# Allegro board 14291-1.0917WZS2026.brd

Outline 221.8 x 181.97 mm; copper layers: TOP, L2VCC, L3, L4, L5GND, BOTTOM. Coordinates in mm from the lower left corner of the outline.

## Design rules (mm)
constraint set DEFAULT: min track width 0.127, pair gap 0.102
net group AUDIO_12MIL: nets CPVEE V3D3_STB
net group AUDIO_BEEP_15MIL: nets AUD_PORTA_L_HPMIC1 AUD_PORTA_R_HPMIC1
net group CL_CLK: nets CL_CLK CL_CLK_R
net group CL_DATA: nets CL_DATA CL_DATA_R
net group CL_RST#: nets CL_RST# CL_RST#_R
net group CLK_PCI_LPC: nets CLK_PCI_LPC PCI_CLK_LPC0
net group CLK_PCI_LPC_MEC: nets CLK_PCI_LPC_MEC PCI_CLK_LPC1
net group CPU_RXN_C_DGPU_TXN0: nets CPU_RXN_C_DGPU_TXN0 DGPU_TXN_CPU_RXN0
net group CPU_RXN_C_DGPU_TXN1: nets CPU_RXN_C_DGPU_TXN1 DGPU_TXN_CPU_RXN1
net group CPU_RXN_C_DGPU_TXN2: nets CPU_RXN_C_DGPU_TXN2 DGPU_TXN_CPU_RXN2
net group CPU_RXN_C_DGPU_TXN3: nets CPU_RXN_C_DGPU_TXN3 DGPU_TXN_CPU_RXN3
net group CPU_RXP_C_DGPU_TXP0: nets CPU_RXP_C_DGPU_TXP0 DGPU_TXP_CPU_RXP0
net group CPU_RXP_C_DGPU_TXP1: nets CPU_RXP_C_DGPU_TXP1 DGPU_TXP_CPU_RXP1
net group CPU_RXP_C_DGPU_TXP2: nets CPU_RXP_C_DGPU_TXP2 DGPU_TXP_CPU_RXP2
net group CPU_RXP_C_DGPU_TXP3: nets CPU_RXP_C_DGPU_TXP3 DGPU_TXP_CPU_RXP3
net group DDR3_A_ODT10_50R-MW: nets M_A_DIMA_ODT0 M_A_DIMA_ODT1
net group DDR3_B_ODT10_50R-MW: nets M_B_DIMB_ODT0 M_B_DIMB_ODT1
net group DGPU_RXN_C_CPU_TXN0: nets DGPU_RXN_C_CPU_TXN0 PEG_TX_CPU_N0
net group DGPU_RXN_C_CPU_TXN1: nets DGPU_RXN_C_CPU_TXN1 PEG_TX_CPU_N1
net group DGPU_RXN_C_CPU_TXN2: nets DGPU_RXN_C_CPU_TXN2 PEG_TX_CPU_N2
net group DGPU_RXN_C_CPU_TXN3: nets DGPU_RXN_C_CPU_TXN3 PEG_TX_CPU_N3
net group DGPU_RXP_C_CPU_TXP0: nets DGPU_RXP_C_CPU_TXP0 PEG_TX_CPU_P0
net group DGPU_RXP_C_CPU_TXP1: nets DGPU_RXP_C_CPU_TXP1 PEG_TX_CPU_P1
net group DGPU_RXP_C_CPU_TXP2: nets DGPU_RXP_C_CPU_TXP2 PEG_TX_CPU_P2
net group DGPU_RXP_C_CPU_TXP3: nets DGPU_RXP_C_CPU_TXP3 PEG_TX_CPU_P3
net group DMIC_CLK_EDP: nets DMIC_PCH_CLK DMIC_PCH_CLK_R
net group DMIC_DATA_EDP: nets DMIC_PCH_DATA DMIC_PCH_DATA_R
net group DP_USB_CPU_PN2: nets USB_CPU_PN2 USB_CPU_PP2
net group DP_USB_CPU_PN5: nets USB_CPU_PN5 USB_CPU_PP5
net group DP_USB_PN0_C: nets USB_PN0_C USB_PP0_C
net group EDP_AUX_CON_N: nets EDP_AUX_CON_N EDP_AUX_CPU_N
net group EDP_AUX_CON_P: nets EDP_AUX_CON_P EDP_AUX_CPU_P
net group EDP_TX_CON_N0: nets EDP_TX_CON_N0 EDP_TX_CPU_N0
net group EDP_TX_CON_N1: nets EDP_TX_CON_N1 EDP_TX_CPU_N1
net group EDP_TX_CON_P0: nets EDP_TX_CON_P0 EDP_TX_CPU_P0
net group EDP_TX_CON_P1: nets EDP_TX_CON_P1 EDP_TX_CPU_P1
net group FBA_VREF: nets FBA_VREF_0 FBA_VREF_1
net group I2C0_SCL_TCH_PAD: nets I2C0_SCL_TCH_PAD I2C1_SCL_R
net group I2C0_SDA_TCH_PAD: nets I2C0_SDA_TCH_PAD I2C1_SDA_R
net group OTHER_4MIL_8MIL: nets HOST_DEBUG_TX ICSP_CLR
net group PCH_SPI_CS2#: nets PCH_SPI_CS2# SPI_CS2#_R
net group PCIE_RX_CON_N6: nets PCIE_RX_CON_N6 PCIE_RX_CPU_N6
net group PCIE_RX_CON_P6: nets PCIE_RX_CON_P6 PCIE_RX_CPU_P6
net group PCIE_TX_CON_N5: nets PCIE_TX_CON_N5 PCIE_TX_CPU_N5
net group PCIE_TX_CON_N6: nets PCIE_TX_CON_N6 PCIE_TX_CPU_N6
net group PCIE_TX_CON_P5: nets PCIE_TX_CON_P5 PCIE_TX_CPU_P5
net group PCIE_TX_CON_P6: nets PCIE_TX_CON_P6 PCIE_TX_CPU_P6
net group PWR_VCCGT_VSN: nets PWR_VCCGT_VSN PWR_VCCGT_VSN_R
net group REF10M: nets PWR_VCCGT_DISB#_A VR_CAP
net group SPI1_HOLD_ROM_R: nets SPI1_HOLD_ROM_R SPI_HOLD_ROM
net group SPI-MWS: nets SPI_HOLD_CPU SPI_HOLD_ROM_R
net group SPI_CS_CPU_N1: nets SPI_CS_CPU_N1 SPI_CS_ROM_N1
net group USB30_TX_CPU_N1: nets USB3_PTX_CRX_N1_R USB30_TX_CPU_N1
net group USB30_TX_CPU_N2: nets USB3_PTX_CRX_N2_R USB30_TX_CPU_N2
net group USB30_TX_CPU_P1: nets USB3_PTX_CRX_P1_R USB30_TX_CPU_P1
net group USB30_TX_CPU_P2: nets USB3_PTX_CRX_P2_R USB30_TX_CPU_P2
net group USB_CON_PN6: nets USB_CON_PN6 USB_CPU_PN6
net group USB_CON_PN7: nets USB_CON_PN7 USB_CPU_PN7
net group USB_CON_PP6: nets USB_CON_PP6 USB_CPU_PP6
net group USB_CON_PP7: nets USB_CON_PP7 USB_CPU_PP7
net group USB_CPU_PN3: nets USB_CPU_PN3 USB_PN3_C
net group USB_CPU_PP3: nets USB_CPU_PP3 USB_PP3_C
net group X_CLK6MIL: nets CFG_RCOMP XCLK_BIASREF
net group AUDIO_BEEP_10MIL: nets AUD_HP1_JACK_L AUD_HP1_JACK_L1 AUD_HP1_JACK_R AUD_HP1_JACK_R1 AUD_PC_BEEP AUD_PC_BEEP_3246 AUD_PC_BEEP_C AUD_PC_BEEP_R AUD_SENSE AUD_SENSE_A AUD_VREF BEEP CBN CBP HDA_SPKR_R JACK_PLUG JACK_PLUG_DET KBC_BEEP_R LINE1-L_C LINE1-L_R LINE1_L LINE1_R LINE1_VREFO_L LINE1_VREFO_R MIC2_VREFO SPKR
net group CARD_12MIL: nets RSET
net group CFG_50R-MW: nets CFG0 CFG1 CFG2 CFG3 CFG4 CFG5 CFG6 CFG7 CFG8 CFG9 CFG10 CFG11 CFG12 CFG13 CFG14 CFG15 CFG16 CFG17 CFG18 CFG19
net group CLK_50R-MW: nets PEXTSTCLK_OUT PEXTSTCLK_OUT# VIDEO_CLK_XTAL_SS WLAN_CLKREQ_WLAN#
net group CODEC_BITCLK_R: nets CODEC_BITCLK_R HDA_BITCLK HDA_CODEC_BITCLK
net group CODEC_SDOUT_R: nets CODEC_SDOUT_R HDA_CODEC_SDOUT HDA_SDOUT
net group COMP_20MIL: nets CPU_POPIRCOMP CSI2_COMP EDP_COMP EMMC_RCOMP PCH_POPIRCOMP USBCOMP
net group CPU_50R-MW: nets CMP_VOUT1 H_PROCHOT# H_PROCHOT#_EC H_PROCHOT#_R H_PROCHOT#_R_R PQ4405_3 PWR_CHG_PROCHOT# VGA_CORE_VID
net group CPU_DP1_CTRL_CLK: nets CPU_DP1_CTRL_CLK
net group CPU_DP1_CTRL_DATA: nets CPU_DP1_CTRL_DATA
net group DDR3_A_CMD_40R-MW: nets M_A_A0 M_A_A1 M_A_A2 M_A_A3 M_A_A4 M_A_A5 M_A_A6 M_A_A7 M_A_A8 M_A_A9 M_A_A10 M_A_A11 M_A_A12 M_A_A13 M_A_A14 M_A_A15 M_A_BS0 M_A_BS1 M_A_BS2 M_A_CAS# M_A_RAS# M_A_WE#
net group DDR3_A_DATA_00_50R-MW: nets M_A_DQ0 M_A_DQ1 M_A_DQ2 M_A_DQ3 M_A_DQ4 M_A_DQ5 M_A_DQ6 M_A_DQ7
net group DDR3_A_DATA_01_50R-MW: nets M_A_DQ8 M_A_DQ9 M_A_DQ10 M_A_DQ11 M_A_DQ12 M_A_DQ13 M_A_DQ14 M_A_DQ15
net group DDR3_A_DATA_02_50R-MW: nets M_A_DQ16 M_A_DQ17 M_A_DQ18 M_A_DQ19 M_A_DQ20 M_A_DQ21 M_A_DQ22 M_A_DQ23
net group DDR3_A_DATA_03_50R-MW: nets M_A_DQ24 M_A_DQ25 M_A_DQ26 M_A_DQ27 M_A_DQ28 M_A_DQ29 M_A_DQ30 M_A_DQ31
net group DDR3_A_DATA_04_50R-MW: nets M_A_DQ32 M_A_DQ33 M_A_DQ34 M_A_DQ35 M_A_DQ36 M_A_DQ37 M_A_DQ38 M_A_DQ39
net group DDR3_A_DATA_05_50R-MW: nets M_A_DQ40 M_A_DQ41 M_A_DQ42 M_A_DQ43 M_A_DQ44 M_A_DQ45 M_A_DQ46 M_A_DQ47
net group DDR3_A_DATA_06_50R-MW: nets M_A_DQ48 M_A_DQ49 M_A_DQ50 M_A_DQ51 M_A_DQ52 M_A_DQ53 M_A_DQ54 M_A_DQ55
net group DDR3_A_DATA_07_50R-MW: nets M_A_DQ56 M_A_DQ57 M_A_DQ58 M_A_DQ59 M_A_DQ60 M_A_DQ61 M_A_DQ62 M_A_DQ63
net group DDR3_B_CMD_40R-MW: nets M_B_A0 M_B_A1 M_B_A2 M_B_A3 M_B_A4 M_B_A5 M_B_A6 M_B_A7 M_B_A8 M_B_A9 M_B_A10 M_B_A11 M_B_A12 M_B_A13 M_B_A14 M_B_A15 M_B_BS0 M_B_BS1 M_B_BS2 M_B_CAS# M_B_RAS# M_B_WE#
net group DDR3_B_DATA_00_50R-MW: nets M_B_DQ0 M_B_DQ1 M_B_DQ2 M_B_DQ3 M_B_DQ4 M_B_DQ5 M_B_DQ6 M_B_DQ7
net group DDR3_B_DATA_01_50R-MW: nets M_B_DQ8 M_B_DQ9 M_B_DQ10 M_B_DQ11 M_B_DQ12 M_B_DQ13 M_B_DQ14 M_B_DQ15
net group DDR3_B_DATA_02_50R-MW: nets M_B_DQ16 M_B_DQ17 M_B_DQ18 M_B_DQ19 M_B_DQ20 M_B_DQ21 M_B_DQ22 M_B_DQ23
net group DDR3_B_DATA_03_50R-MW: nets M_B_DQ24 M_B_DQ25 M_B_DQ26 M_B_DQ27 M_B_DQ28 M_B_DQ29 M_B_DQ30 M_B_DQ31
net group DDR3_B_DATA_04_50R-MW: nets M_B_DQ32 M_B_DQ33 M_B_DQ34 M_B_DQ35 M_B_DQ36 M_B_DQ37 M_B_DQ38 M_B_DQ39
net group DDR3_B_DATA_05_50R-MW: nets M_B_DQ40 M_B_DQ41 M_B_DQ42 M_B_DQ43 M_B_DQ44 M_B_DQ45 M_B_DQ46 M_B_DQ47
net group DDR3_B_DATA_06_50R-MW: nets M_B_DQ48 M_B_DQ49 M_B_DQ50 M_B_DQ51 M_B_DQ52 M_B_DQ53 M_B_DQ54 M_B_DQ55
net group DDR3_B_DATA_07_50R-MW: nets M_B_DQ56 M_B_DQ57 M_B_DQ58 M_B_DQ59 M_B_DQ60 M_B_DQ61 M_B_DQ62 M_B_DQ63
net group DDR3_CKE_40R-MW: nets M_A_CKE0 M_A_CKE1 M_A_CS#0 M_A_CS#1 M_B_CKE0 M_B_CKE1 M_B_CS#0 M_B_CS#1
net group DDR3_VREF_40MIL: nets M_VREF_DQ_DIM0 M_VREF_DQ_DIM1 V_SM_VREF_CNT
net group EC_SPI_CLK: nets EC_SPI_CLK SPI1_CLK_ROM_R SPI_CLK_CPU SPI_CLK_ROM SPI_CLK_ROM_R SPI_CLK_ROM_TPM
net group EC_SPI_CS0#: nets EC_SPI_CS0# SPI_CS_CPU_N0 SPI_CS_ROM_N0
net group EC_SPI_MISO: nets EC_SPI_MISO SPI1_SO_ROM_R SPI_SO_CPU SPI_SO_ROM SPI_SO_ROM_R SPI_SO_ROM_TPM
net group EC_SPI_MOSI: nets EC_SPI_MOSI SPI1_SI_ROM_R SPI_SI_CPU SPI_SI_ROM SPI_SI_ROM_R SPI_SI_ROM_TPM
net group FAN_TACH_10MIL: nets FAN1_TACH FAN_TACH1 FAN_TACH1_C
net group FFS-MW: nets FALL_INT2 FFS_INT2 FFS_INT2_Q HDD_FALL_INT
net group GND: nets EC_AGND
net group H_CPU_SVIDALRT#: nets H_CPU_SVIDALRT# PWR_VCORE_ALERT# VR_SVID_ALERT#
net group H_CPU_SVIDCLK: nets H_CPU_SVIDCLK PWR_VCORE_SCLK VR_SVID_CLK
net group H_CPU_SVIDDAT: nets H_CPU_SVIDDAT PWR_VCORE_SDIO VR_SVID_DATA
net group HDA_CODEC_RST#: nets HDA_CODEC_RST# HDA_CODEC_RST#_R HDA_RST#
net group HDA_CODEC_SDIN0: nets HDA_SDIN0
net group HDA_CODEC_SYNC: nets HDA_SYNC
net group HDMI_CLK: nets HDMI_CLK HDMI_CLK_R HDMI_CLK_R_C
net group HDMI_CLK#: nets HDMI_CLK# HDMI_CLK#_R HDMI_CLK#_R_C
net group HDMI_DATA0: nets HDMI_DATA0 HDMI_DATA0_R HDMI_DATA0_R_C
net group HDMI_DATA0#: nets HDMI_DATA0# HDMI_DATA0#_R HDMI_DATA0#_R_C
net group HDMI_DATA1: nets HDMI_DATA1 HDMI_DATA1_R HDMI_DATA1_R_C
net group HDMI_DATA1#: nets HDMI_DATA1# HDMI_DATA1#_R HDMI_DATA1#_R_C
net group HDMI_DATA2: nets HDMI_DATA2 HDMI_DATA2_R HDMI_DATA2_R_C
net group HDMI_DATA2#: nets HDMI_DATA2# HDMI_DATA2#_R HDMI_DATA2#_R_C
net group JTAG: nets PCH_JTAG_TCK PCH_JTAG_TDI PCH_JTAG_TDO PCH_JTAG_TMS
net group KB: nets KSI0 KSI1 KSI2 KSI3 KSI4 KSI5 KSI6 KSI7 KSO0 KSO1 KSO2 KSO3 KSO4 KSO5 KSO6 KSO7 KSO8 KSO9 KSO10 KSO11 KSO12 KSO13 KSO14 KSO15 KSO16
net group LCD_BKLT-MW: nets BKLT_CTRL EDP_BKLT_CTRL L_BKLT_CTRL LCD_BRIGHTNESS LED_SATA_DIAG_OUT# MASK_BASE_LEDS#
net group LED: nets BAT1_LED# BAT2_LED# BATT_WHITE_LED# BATT_WHITE_LED_R# CAP_LED# CAP_LED#_S CAP_LED_R# CHG_AMBER_LED# CHG_AMBER_LED_R# PWR_LED# PWR_LED#_B PWR_LED#_S SATA_LED# SATA_LED#_B
net group LED_20MIL: nets AMBER_LED_BAT BAT_AMBER BAT_WHITE BATT_WHITE_LED#_M CAP_LED CAP_LED_Q CHG_AMBER_LED#_M PWR_LED PWR_LED#_R SATA_LED SATA_LED#_M SATA_LED_R WHITE_LED_BAT
net group LPC_50R-MWS: nets CLKRUN#_R LPC_FRAME#_DEBUG LPC_LAD0 LPC_LAD0_C LPC_LAD0_R LPC_LAD1 LPC_LAD1_C LPC_LAD1_R LPC_LAD2 LPC_LAD2_C LPC_LAD2_R LPC_LAD3 LPC_LAD3_C LPC_LAD3_R LPC_LFRAME# LPC_LFRAME#_R
net group OTHER_4MIL: nets 1D05V_VGA_S0_DISCHG 3D3V_VGA_S0_DISCHG 3V3_AON_S0_DISCHG +3VLP AC_IN#_G AC_IN_KBC# AC_IN_KBC#_R AC_PRESENT AD+_G_1 AD_IA BKLGT_PWM BLON_OUT_C BLUETOOTH_EN BLUETOOTH_EN_NGFF BOARD_ID BOARD_ID2 BOARD_ID3 BOARD_ID_C BUFRST# CLKREQ_PCIE#1 CLKREQ_PCIE#2 CLKREQ_PCIE#3 CLKREQ_PCIE#4 CLKREQ_PCIE#5 CLKREQ_PEG#0 CLKRUN# CMP_STRAP0 COMBO-GPI CPU_DP1_HPD CPU_DP2_HPD CPU_DP2_HPD1 CPU_DP2_HPD3 DBC_EN_R DBC_PANEL_EN DDPD_CTRLDATA DDR0_PAR DDR1_PAR DGPU_PWR_EN# DVSS E51_RX1 E51_RX2 E51_TX1 E51_TXD_R EC_MUTE# EC_WAKE# EDP_DISP_UTIL EDP_HPD EDP_HPD_CONN FB_VREF FBA_DEBUG0 FBA_DEBUG1 GPD2/LAN_WAKE# GPP_B2/VRALERT# GPP_B4/CPU_GP3 GPP_B18/GSPI0_MOSI GPP_B23/SML1ALERT# GPP_C2/SMBALERT# GPP_C5/SML0ALERT# GPP_E0/SATAXPCIE0/SATAGP0 GPP_E1/SATAXPCIE1/SATAGP1 GPP_E2/SATAXPCIE2/SATAGP2 GPP_E3/CPU_GP0 H_CATERR# H_THERMTRIP# H_THERMTRIP_EN HDD_DEVSLP HDD_DEVSLP_R HDMI_HPD_B HDMI_HPD_E HPD_HDMI_CON I_ADP ICSP_CLR_R IFPAB_IOVDD IFPAB_PLLVDD IFPC_IOVDD IFPC_PLLVDD IFPD_IOVDD IFPD_PLLVDD IFPEF_IOVDD IFPEF_PLLVDD INT_TP# ISOLATE# ITP_PMODE JDREF KB_DET# KB_LED_BL_DET KB_LED_DET_C KBC_PWRBTN# L_BKLT_EN L_BKLT_EN_EC LCD_TST LCD_TST_C LCD_TST_EN LCDVDD_EN LED0 LED1 LED2 LID_CL_SIO# LID_CLOSE#_C ME_FWP_EC MESW1_B MODEL_ID MODEL_ID_C MSM# N12P_JTAG_TCK N12P_JTAG_TDI N12P_JTAG_TDO N12P_JTAG_TMS N12P_JTAG_TRST N12P_XTAL_OUTBUFF NCT7718_ALERT# NCTF_A5 NCTF_A70 NCTF_B71 NCTF_BA1 NCTF_BA2 NCTF_BA71 NCTF_BB70 NCTF_C1 P2800_VGA_DXN P2800_VGA_DXP P_SYS PANEL_BKEN_EC PANEL_SIZE_ID PANEL_SIZE_ID_CONN PBAT_PRES1# PBAT_PRES# PCH_BATLOW# PCH_PLTRST# PCH_PLTRST#_EC PCH_THERMTRIP PCH_WAKE# PD4403_A PD4403_K PD# PEX_TERMP PIRQA# PLT_RST# PLT_RST_NGFF# PME# POWER_SW_IN# PQ4405_2 PQ4405_5 PQ4405_6 PQ4408_C PQ4408_E PROC_SELECT# PROJECT_ID1 PROJECT_ID2 PS_ID PS_ID_R PSYS PTP_DIS# PTP_INT#_EC PWR_5V_VCLK PWR_CHG_ACOK PWR_CHG_AD_OFF_R PWR_CHG_ILIM Q402_1 Q4009_G Q7601_G RISING TIME RISING TIME2 RTC_DET# SA0_DIMA SA0_DIMB SA1_DIMA SA1_DIMB SERIRQ_TPM SIO_PWRBTN# SIO_RCIN# SIO_SLP_SUS# SKTOCC# SM_INTRUDER# SPI_IRQ# TESTMODE TOUCHPAD_INTR# TP_RESET TP_RS USB_OC0# USB_OC1# USB_OC2# USB_OC3# USB_UART_SEL_D9 VCC_OPC_1P8_H63 VCI_IN1# VCREF0 VGA_CORE_DISCHG VR_EN VR_RDY VRAM_ID1 VRAM_ID2 WIFI_RF_EN WLAN_DISABLE#1 XDP_PWRBTN# ZVM#
net group PECI-MW: nets AUX_EN_WOWL AUX_EN_WOWL_R H_PECI HDD_PWR_EN PECI_EC
net group PLATFORM: nets 1D0V_S5_PWRGD 1D05V_VGA_EN 1D05V_VGA_EN# 1D05V_VGA_S0_PWRGD 1D8A_EN# 1D8A_EN_R# 1D8V_EN# 1D8V_EN_R# 1D8V_S5_PWROK 1D35V_ENABLE 1D35V_ENABLE_RC 1D35V_ENABLE_TP 1D35V_VGA_EN 1D35V_VGA_EN# 1D35V_VTT_PWRGD 3.3V_WLAN_EN 3.3V_WLAN_ENABLE 3.3V_WLAN_ENABLE# 3V5V_S0_ON 3V_5V_EN 3V_5V_POK 3V_5V_POK# 3V_5V_POK_C 5V_HDD_ENABLE 5V_HDD_ENABLE# ACAV_IN ALL_SYS_PWRGD ALWON CLK_LAN_REQ4#_R CLK_LAN_REQ#_EN DDR3_DRAMRST# DDR_VTT_PG_CTRL_R DGPU_HOLD_RST# DGPU_PWR_EN DGPU_PWROK DGPU_PWROK_KBC DS3_PWRCTL EDP_VDD_EN EXT_PWR_GATE# GC6_FB_EN GC6_FB_EN_GPU GC6_FB_EN_MCP GPIO5_GC6_PWR_EN GPIO5_GC6_PWR_EN# GPIO5_GC6_PWR_EN_GPU GPIO9_ALERT GPIO10_FBVREF GPU_CLKREQ# GPU_EVENT# GPU_EVENT_GPU# GPU_EVENT_MCP# GPU_PEX_RST# GPU_PEX_RST_D# GPU_PEX_RST_HOLD GPU_PEX_RST_HOLD_GPU# H_CPUPWRGD H_VCCST_PWRGD H_VCCST_PWRGD_R HDD_DET# HDD_PWR_EN_R IR_CAMERA_DET# IR_CAMERA_DET#_R KBC_PWRBTN#_C LAN_EN LAN_ENABLE_R_C LCD_CBL_DET# LCD_CBL_DET#_R LOM_CABLE_DETECT# ME_SUS_PWR_ACK ME_SUS_PWR_ACK_R OVERT# OVERT_GPU# PCH_ALW_ON PCH_DPWROK PCH_RSMRST# PCIE_LAN_WAKE# PCIE_WAKE# PCIE_WLAN_WAKE# PCIE_WLAN_WAKE#_R PLT_RST#_DEBUG PLT_RST#_LAN PM_LAN_ENABLE PM_LAN_ENABLE_C PM_PCH_PWROK PM_RSMRST# PM_RSMRST#_M PM_RSMRST#_R PM_SLP_S0_STG# PM_SLP_S3_STG# PS_S3CNTRL PWR_1D0V_EN PWR_1D0V_PG PWR_1D5V_EN PWR_1D05V_PGOOD PWR_1D8V_EN PWR_1D8V_POK PWR_1D35V_EN PWR_3D3V_EN2 PWR_5V_EN1 PWR_5V_EN1_R PWR_LEVEL PWR_VCCIO_EN PWR_VCORE_EN PWR_VGA_CORE_EN# Q9101.G RESET_OUT# ROM_CS# ROM_SCLK ROM_SI ROM_SO RSMRST_PWRGD# RTC_RST# RTCRST_ON RUNPWROK SD_READ_MODE# SERIRQ SIO_EXT_SCI# SIO_EXT_SCI#_R SIO_EXT_SMI# SIO_EXT_SMI#_R SIO_SLP_A# SIO_SLP_S0# SIO_SLP_S3# SIO_SLP_S4# SIO_SLP_S5# SLP_LAN# SM_DRAMRST# SM_PGCNTL SRTC_RST# STRAP0 STRAP1 STRAP2 STRAP3 STRAP4 STRAP_REF0_GND_N9 SUS_STAT#/LPCPD# SUSACK# SUSACK#_R SYS_PEX_RST_MON# SYS_PEX_RST_MON_GPU# SYS_PWROK TOUCH_PANEL_INTR# TP_EN# TP_LOCK# TP_ON#_GATE TPM_GPIO0 TPM_GPIO2 TPM_GPIO4 USB_EN# USB_PWR_EN# VCCSTG_EN VCCSTG_EN_D VCCSTG_EN_R VCCSTU_EN VCCSTU_EN_D VCCSTU_EN_R VGA_CORE_PSI VIDEO_THERM_OVERT#
net group POWER_10M: nets 1.8V_RUN_FB 3D3V_VGA_CT_1 3V3_AON_CT_2 +VCC19P2_1P0 +VCC24TBT_1P0 +VCCAMPHYPLL_1P0 +VCCAPLL_1P0 +VCCDSW_1P0 +VCCDTS_1P0 +VCCF24NS_1P0_L +VCCF100_1P0_L +VCCF100OC_1P0_L +VCCFHV +VCCPAZIO +VCCPDSW_3P3 +VCCPGPPA +VCCPGPPB +VCCPGPPC +VCCPGPPD +VCCPGPPD_TCH +VCCPGPPE +VCCPGPPF +VCCPGPPG +VCCPRIM_3P3 +VCCPRTC_3P3 +VCCPRTCPRIM_3P3 +VCCPSPI +VCCST_CPU +VCCSTG +VDDQ_CPU_CLK ACOK_IN AD+_G_2 BOOST_MON FAN1_DAC_1 FB_CLAM FBA_ZQ0 FBA_ZQ1 FBA_ZQ2 FBA_ZQ3 FP_PWR I_BATT I_SYS LDO1_CAP LDO2_CAP LDO3_CAP MIC_CAP PQ3808D PQ3808G PQ4303_5 PWR_1D35V_VDDQS PWR_CHG_1 PWR_CHG_BATPRES# PWR_CHG_BATSRC PWR_CHG_CMSRC PWR_CHG_IADP PWR_CHG_IDCHG PWR_CHG_PMON PWR_CHG_STAT# PWR_VCCGT_COMP PWR_VCCGT_COMP_R PWR_VCCGT_CSCOMP PWR_VCCGT_CSNA PWR_VCCGT_CSP1 PWR_VCCGT_CSP2 PWR_VCCGT_CSPA PWR_VCCGT_CSREF PWR_VCCGT_CSSUM PWR_VCCGT_DIFFOUT PWR_VCCGT_FB PWR_VCCGT_FB_R PWR_VCCGT_ICCMAX PWR_VCCGT_ILIM PWR_VCCGT_ILIM_R PWR_VCCGT_IOUT PWR_VCCGT_NTC PWR_VCCGT_PWMA PWR_VCCGT_TSENSE PWR_VCCGT_VCCA PWR_VCCGT_VSP PWR_VCCSA_COMP PWR_VCCSA_COMP_R PWR_VCCSA_CSN PWR_VCCSA_CSN_NTC PWR_VCCSA_CSP PWR_VCCSA_CSP1B PWR_VCCSA_ICCMAX PWR_VCCSA_ILIM PWR_VCCSA_IOUT PWR_VCCSA_VSP_RC PWR_VCORE_COMP PWR_VCORE_COMP_R PWR_VCORE_CSN PWR_VCORE_CSNNTC PWR_VCORE_CSP PWR_VCORE_CSP_1A PWR_VCORE_DRVON PWR_VCORE_ICCMAX PWR_VCORE_ILIM PWR_VCORE_IOUT PWR_VCORE_NTC PWR_VCORE_ROSC_COREGT PWR_VCORE_ROSC_SAUS PWR_VCORE_TSENSE PWR_VCORE_VCC_R PWR_VCORE_VR_RDY PWR_VCORE_VRHOT# PWR_VCORE_VRMP PWR_VCORE_VSN PWR_VCORE_VSN_R PWR_VCORE_VSP PWR_VCORE_VSP_R PWR_VCORE_VSP_RC PWR_VGA_CORE_EN PWR_VGA_CORE_PSI PWR_VGA_CORE_REFIN PWR_VGA_CORE_VID PWR_VGA_CORE_VREF Q6204_G REFIN_VREF V0.85A_VID0 V0.85A_VID1 VCCRTCEXT
net group POWER_10M_POWER: nets 3V_FEEDBACK AC_DIS AD_OFF_L AD_OFF_R BT+_1 PQ3809_D PR4601_1 PU4301_G PWR_1D0V_BYP PWR_1D0V_FB PWR_1D0V_ILMT PWR_1D0V_LDO PWR_1D35V_MODE PWR_1D35V_REFIN PWR_1D35V_TRIP PWR_1D35V_VREF PWR_3D3V_CS2 PWR_3D3V_FB2 PWR_3D3V_FB2_R PWR_5V_CS1 PWR_5V_FB1 PWR_5V_FB1_R PWR_CHG_ACDET PWR_CHG_CMPIN PWR_CHG_CMPOUT PWR_CHG_REGN PWR_CHG_VCC PWR_VCORE_ADDR_BOOT PWR_VCORE_DISB# PWR_VGA_CORE_REFADJ PWR_VGA_CORE_SS PWR_VGA_CORE_TON PWR_VGA_CORE_TON_1 VCCIO_VR_FB VSS_AY71 VSSIO_VR_FB
net group POWER_15M: nets 3D3V_TP_S5_R +VCCMPHYAON_1P0 Q6205_Q
net group POWER_20M: nets 1D8V_S0 3D3V_AUX_KBC_33 3D3V_AUX_KBC_R 3D3V_AUX_S5 +5V_AVDD +RTC_VCC +V_VREF_PATH1 +V_VREF_PATH2 +V_VREF_PATH3 DC_IN_D EC_VTT GPU_PLL_VDD MCT0 MCT1 MCT2 MCT3 PR4605_2 PWR_1D05V_EN PWR_1D05V_FB PWR_1D35V_VBST PWR_3D3V_VBST2 PWR_3D3V_VBST2_1 PWR_5V_VBST1 PWR_5V_VBST1_1 PWR_5V_VO1 PWR_CHG_BTST PWR_VCCGT_SNUB_1 RTC_PWR VCC1R05VIDEO_PEX_PLLVDD
net group POWER_20M_POWER: nets 3D3V_PWR_2 5V_PWR_2 PWR_3D3V_SNUB PWR_5V_SNUB PWR_VCCGT_BOOTA_RC PWR_VCCSA_BST PWR_VCCSA_BST_RC PWR_VCCSA_PWM PWR_VCCSA_SNUB PWR_VCORE_BOOT_RC PWR_VCORE_PWM PWR_VCORE_SNUB PWR_VCORE_VCC PWR_VGA_CORE_BOOT1 PWR_VGA_CORE_BOOT1_1 PWR_VGA_CORE_BOOT2 PWR_VGA_CORE_BOOT2_1 PWR_VGA_SNUB1 PWR_VGA_SNUB2
net group POWER_40M: nets +UZ12_TPM DIS_1D35V_VGA_S0 LOM_TCT TPM_VDD14 TPM_VDD22 TPM_VSB
net group POWER_120MIL-MW: nets +VCCAPLLEBB_1P0
net group POWER_160M: nets RT8812_PVCC
net group POWER_240M_POWER: nets PWR_1D05V_SVIN
net group POWER_320M_POWER: nets AC_DIS_M
net group PWR_VCCSA_VSN: nets PWR_VCCSA_VSN PWR_VCCSA_VSN_R VSSSA_SENSE
net group PWR_VCCSA_VSP: nets PWR_VCCSA_VSP PWR_VCCSA_VSP_R VCCSA_SENSE
net group SATA_RX_CON_N0: nets SATA_RX_CPU_N0
net group SATA_RX_CON_P0: nets SATA_RX_CPU_P0
net group SATA_TX_CON_N0: nets SATA_TX_CPU_N0
net group SATA_TX_CON_P0: nets SATA_TX_CPU_P0
net group SMBUS_50R-MWS: nets CLK_TP_SIO CPU_DP2_CTRL_CLK CPU_DP2_CTRL_DATA DAT_TP_SIO DDC_CLK_PH1 DDC_DATA_PH2 DMIC_CLK DMIC_CLK_R DMIC_DATA DMIC_DATA_R I2C0_SCL I2C0_SDA I2C1_SCL I2C1_SDA I2CA_SCL I2CA_SDA I2CB_SCL I2CB_SDA I2CC_SCL I2CC_SDA ICSP_CLK_R ICSP_CLOCK ICSP_DATA ICSP_DATA_R MEM_SMBCLK MEM_SMBDATA PBAT_SMBCLK1 PBAT_SMBDAT1 PCH_SMBCLK PCH_SMBDATA PWR_CHG_SCL PWR_CHG_SDA SMBC_THERM_NV SMBCLK1 SMBCLK2 SMBD_THERM_NV SMBDA1 SMBDA2 SML0_SMBCLK SML0_SMBDATA SML1_SMBCLK SML1_SMBDATA THM_SML1_CLK THM_SML1_DATA TPCLK_C TPDATA_C XDP_SMBCLK XDP_SMBDAT
net group SPI1_WP_ROM_R: nets SPI1_WP_ROM_R SPI_WP_CPU SPI_WP_ROM SPI_WP_ROM_R
net group SUSCLK_R: nets SUS_CLK SUSCLK_R XTAL2
net group T8_50R-MW: nets CMP_VIN0 CMP_VIN0_R VD_IN1_C
net group TESTPOINT_4MIL: nets CPU_A16_TP CPU_D1_TP CPU_D4_TP CPU_D5_TP CPU_D6_TP RSVD_F65 RSVD_G65 RSVD_TP_AK12 RSVD_TP_AK13 RSVD_TP_AW70 RSVD_TP_AW71 RSVD_TP_BA68 RSVD_TP_BA70 RSVD_TP_BB68 RSVD_TP_BB69 TP1_AY4 TP2_BB3 TP4_BB5 TP5_AU5 TP6_AT5
net group THERM_10M: nets FON#
net group THERM_SHUTDOWN: nets CMP_VOUT0 OVER_CURRENT_P8# P_H_S# PURE_HW_SHUTDOWN# T_CRIT# THERM_SYS_SHDN#
net group UART-MWS: nets LPSS_UART2_CTS# LPSS_UART2_RXD LPSS_UART2_TXD SIO_EXT_WAKE# UART0_CTS# UART0_RTS# UART0_TXD UART1_CTS# UART1_RTS# UART1_RXD
net group USB30_RX_CPU_N1: nets USB30_RX_CPU_N1
net group USB30_RX_CPU_N2: nets USB30_RX_CPU_N2
net group USB30_RX_CPU_P1: nets USB30_RX_CPU_P1
net group USB30_RX_CPU_P2: nets USB30_RX_CPU_P2
net group VRAM_CMD_45R-MWS: nets FBA_CMD0 FBA_CMD1 FBA_CMD2 FBA_CMD3 FBA_CMD4 FBA_CMD5 FBA_CMD6 FBA_CMD7 FBA_CMD8 FBA_CMD9 FBA_CMD10 FBA_CMD11 FBA_CMD12 FBA_CMD13 FBA_CMD14 FBA_CMD15 FBA_CMD16 FBA_CMD17 FBA_CMD18 FBA_CMD19 FBA_CMD20 FBA_CMD21 FBA_CMD22 FBA_CMD23 FBA_CMD24 FBA_CMD25 FBA_CMD26 FBA_CMD27 FBA_CMD28 FBA_CMD29 FBA_CMD30 FBA_CMD31
net group VRAM_DBI_45R-MWS: nets FBA_DQM0 FBA_DQM1 FBA_DQM2 FBA_DQM3 FBA_DQM4 FBA_DQM5 FBA_DQM6 FBA_DQM7
net group VRAM_DQ_45R-MW: nets FBA_D0 FBA_D1 FBA_D2 FBA_D3 FBA_D4 FBA_D5 FBA_D6 FBA_D7 FBA_D8 FBA_D9 FBA_D10 FBA_D11 FBA_D12 FBA_D13 FBA_D14 FBA_D15 FBA_D16 FBA_D17 FBA_D18 FBA_D19 FBA_D20 FBA_D21 FBA_D22 FBA_D23 FBA_D24 FBA_D25 FBA_D26 FBA_D27 FBA_D28 FBA_D29 FBA_D30 FBA_D31 FBA_D32 FBA_D33 FBA_D34 FBA_D35 FBA_D36 FBA_D37 FBA_D38 FBA_D39 FBA_D40 FBA_D41 FBA_D42 FBA_D43 FBA_D44 FBA_D45 FBA_D46 FBA_D47 FBA_D48 FBA_D49 FBA_D50 FBA_D51 FBA_D52 FBA_D53 FBA_D54 FBA_D55 FBA_D56 FBA_D57 FBA_D58 FBA_D59 FBA_D60 FBA_D61 FBA_D62 FBA_D63
net group XDP-MW: nets SPI0_MOSI_XDP XDP_DBRESET# XDP_PRDY# XDP_PREQ# XDP_SPI0_IO2 XDP_TCK_JTAGX XDP_TDI XDP_TDO_CPU XDP_TMS XDP_TRST#
net group XDP_BPM-MW: nets XDP_BPM0 XDP_BPM1 XDP_BPM2 XDP_BPM3
net group XDP_TCLK-MW: nets XDP_TCLK
net group XTAL-MW: nets 27MHZ_OUT_R LANXIN LANXOUT RTC_X1 RTC_X2 XTAL1 XTAL24_IN XTAL24_IN_R XTAL24_OUT XTAL_KBC_2

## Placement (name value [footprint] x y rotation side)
AFTP2501  AFTE14P-GP  [AFTE14P-75]  14.43 21.42 0 top
AFTP2502  AFTE14P-GP  [AFTE14P-75]  81.52 9.47 0 top
AFTP2801  AFTE14P-GP  [AFTE14P-75]  96.79 137.64 0 top
AFTP2802  AFTE14P-GP  [AFTE14P-75]  98.81 144.12 0 top
AFTP2803  AFTE14P-GP  [AFTE14P-75]  82.53 153.68 0 top
AFTP2901  AFTE14P-GP  [AFTE14P-75]  42.06 10.49 0 top
AFTP2902  AFTE14P-GP  [AFTE14P-75]  43.46 11.79 0 top
AFTP2903  AFTE14P-GP  [AFTE14P-75]  42.02 7.86 0 top
AFTP2904  AFTE14P-GP  [AFTE14P-75]  43.43 9.16 0 top
AFTP3101  AFTE14P-GP  [AFTE14P-75]  13.97 169.09 0 top
AFTP3102  AFTE14P-GP  [AFTE14P-75]  12.65 167.66 0 top
AFTP3103  AFTE14P-GP  [AFTE14P-75]  14.63 173 0 top
AFTP3104  AFTE14P-GP  [AFTE14P-75]  12.71 172.53 0 top
AFTP3105  AFTE14P-GP  [AFTE14P-75]  14.75 176.01 0 top
AFTP3106  AFTE14P-GP  [AFTE14P-75]  13.93 171.02 0 top
AFTP3107  AFTE14P-GP  [AFTE14P-75]  14.77 167.04 0 top
AFTP3108  AFTE14P-GP  [AFTE14P-75]  12.91 175.33 0 top
AFTP3401  AFTE14P-GP  [AFTE14P-75]  16.39 43.81 0 top
AFTP3402  AFTE14P-GP  [AFTE14P-75]  14.8 42.74 0 top
AFTP3403  AFTE14P-GP  [AFTE14P-75]  14.72 40.23 0 top
AFTP3404  AFTE14P-GP  [AFTE14P-75]  13.88 29.69 0 top
AFTP3405  AFTE14P-GP  [AFTE14P-75]  14.91 27.52 0 top
AFTP3406  AFTE14P-GP  [AFTE14P-75]  14.4 25.69 0 top
AFTP3801  AFTE14P-GP  [AFTE14P-75]  87.62 159.54 0 top
AFTP3802  AFTE14P-GP  [AFTE14P-75]  102.09 169.88 0 top
AFTP3803  AFTE14P-GP  [AFTE14P-75]  95.24 159.58 0 top
AFTP3805  AFTE14P-GP  [AFTE14P-75]  85.72 159.54 0 top
AFTP3806  AFTE14P-GP  [AFTE14P-75]  93.33 159.58 0 top
AFTP3807  AFTE14P-GP  [AFTE14P-75]  85.9 157.51 0 top
AFTP3902  AFTE14P-GP  [AFTE14P-75]  155.52 176.58 0 top
AFTP3903  AFTE14P-GP  [AFTE14P-75]  157.39 174.66 0 top
AFTP3904  AFTE14P-GP  [AFTE14P-75]  157.43 176.59 0 top
AFTP3905  AFTE14P-GP  [AFTE14P-75]  148.93 175.33 0 top
AFTP3906  AFTE14P-GP  [AFTE14P-75]  141.92 178.76 0 top
AFTP3907  AFTE14P-GP  [AFTE14P-75]  142.15 175.01 0 top
AFTP3908  AFTE14P-GP  [AFTE14P-75]  142.55 173.07 0 top
AFTP3909  AFTE14P-GP  [AFTE14P-75]  139.95 178.85 0 top
AFTP3910  AFTE14P-GP  [AFTE14P-75]  151.17 176 0 top
AFTP5601  AFTE14P-GP  [AFTE14P-75]  184.97 32.52 0 top
AFTP5801  AFTE14P-GP  [AFTE14P-75]  167.3 62.51 0 top
AFTP5802  AFTE14P-GP  [AFTE14P-75]  159.7 52.51 0 top
AFTP5803  AFTE14P-GP  [AFTE14P-75]  162.27 53.13 0 top
AFTP5804  AFTE14P-GP  [AFTE14P-75]  164.19 53.12 0 top
AFTP5805  AFTE14P-GP  [AFTE14P-75]  165.89 54.26 0 top
AFTP5806  AFTE14P-GP  [AFTE14P-75]  158.24 61.57 0 top
AFTP5807  AFTE14P-GP  [AFTE14P-75]  158.14 63.5 0 top
AFTP6101  AFTE14P-GP  [AFTE14P-75]  216.91 154.67 0 top
AFTP6102  AFTE14P-GP  [AFTE14P-75]  212.24 171.48 0 top
AFTP6103  AFTE14P-GP  [AFTE14P-75]  214.98 154.72 0 top
AFTP6104  AFTE14P-GP  [AFTE14P-75]  218.84 154.67 0 top
AFTP6201  AFTE14P-GP  [AFTE14P-75]  190.86 119.08 0 top
AFTP6202  AFTE14P-GP  [AFTE14P-75]  177.11 89.04 0 top
AFTP6203  AFTE14P-GP  [AFTE14P-75]  192.21 112.94 0 top
AFTP6206  AFTE14P-GP  [AFTE14P-75]  181.99 85.12 0 top
AFTP6207  AFTE14P-GP  [AFTE14P-75]  192.22 108.55 0 top
AFTP6208  AFTE14P-GP  [AFTE14P-75]  192.23 104.7 0 top
AFTP6213  AFTE14P-GP  [AFTE14P-75]  192.25 101.86 0 top
AFTP6214  AFTE14P-GP  [AFTE14P-75]  192.23 95.85 0 top
AFTP6215  AFTE14P-GP  [AFTE14P-75]  192.25 99.89 0 top
AFTP6216  AFTE14P-GP  [AFTE14P-75]  192.23 114.88 0 top
AFTP6217  AFTE14P-GP  [AFTE14P-75]  15.03 36.89 0 top
AFTP6218  AFTE14P-GP  [AFTE14P-75]  192.22 93.94 0 top
AFTP6219  AFTE14P-GP  [AFTE14P-75]  193.94 115.84 0 top
AFTP6220  AFTE14P-GP  [AFTE14P-75]  192.25 116.83 0 top
AFTP6221  AFTE14P-GP  [AFTE14P-75]  177.41 85.12 0 top
AFTP6222  AFTE14P-GP  [AFTE14P-75]  178.61 86.59 0 top
AFTP6223  AFTE14P-GP  [AFTE14P-75]  185.69 86.36 0 top
AFTP6224  AFTE14P-GP  [AFTE14P-75]  183.45 86.38 0 top
AFTP6225  AFTE14P-GP  [AFTE14P-75]  193.94 111.92 0 top
AFTP6226  AFTE14P-GP  [AFTE14P-75]  192.23 106.62 0 top
AFTP6227  AFTE14P-GP  [AFTE14P-75]  192.25 97.98 0 top
AFTP6228  AFTE14P-GP  [AFTE14P-75]  181 87.05 0 top
AFTP6229  AFTE14P-GP  [AFTE14P-75]  193.88 113.92 0 top
AFTP6230  AFTE14P-GP  [AFTE14P-75]  190.82 92.62 0 top
AFTP6231  AFTE14P-GP  [AFTE14P-75]  187.6 86.19 0 top
AFTP6232  AFTE14P-GP  [AFTE14P-75]  194.58 118.28 0 top
AFTP6233  AFTE14P-GP  [AFTE14P-75]  192.23 110.47 0 top
AFTP6234  AFTE14P-GP  [AFTE14P-75]  179.79 85.1 0 top
AFTP6235  AFTE14P-GP  [AFTE14P-75]  56.81 81.22 0 top
AFTP6236  AFTE14P-GP  [AFTE14P-75]  56.76 79.28 0 top
AFTP6237  AFTE14P-GP  [AFTE14P-75]  58.52 75.18 0 top
AFTP6238  AFTE14P-GP  [AFTE14P-75]  58.51 80.2 0 top
AFTP6239  AFTE14P-GP  [AFTE14P-75]  58.52 73.27 0 top
AFTP6240  AFTE14P-GP  [AFTE14P-75]  56.72 74.04 0 top
AFTP6241  AFTE14P-GP  [AFTE14P-75]  57.34 76.69 0 top
AFTP6242  AFTE14P-GP  [AFTE14P-75]  58.52 78.23 0 top
AFTP6243  AFTE14P-GP  [AFTE14P-75]  192.77 119.06 0 top
AFTP6244  AFTE14P-GP  [AFTE14P-75]  14.42 23.34 0 top
AFTP6245  AFTE14P-GP  [AFTE14P-75]  184.97 41.86 0 top
AFTP6246  AFTE14P-GP  [AFTE14P-75]  194.13 101.24 0 top
AFTP6247  AFTE14P-GP  [AFTE14P-75]  194.12 105.05 0 top
AFTP6248  AFTE14P-GP  [AFTE14P-75]  194.11 103.15 0 top
AFTP6301  AFTE14P-GP  [AFTE14P-75]  184.93 26.37 0 top
AFTP6302  AFTE14P-GP  [AFTE14P-75]  183.13 26.99 0 top
AFTP6303  AFTE14P-GP  [AFTE14P-75]  184.97 30.61 0 top
AFTP6304  AFTE14P-GP  [AFTE14P-75]  183.54 29.33 0 top
AFTP6305  AFTE14P-GP  [AFTE14P-75]  184.74 123.1 0 top
AFTP6306  AFTE14P-GP  [AFTE14P-75]  186.66 123.31 0 top
AFTP6307  AFTE14P-GP  [AFTE14P-75]  189.76 123.75 0 top
AFTP6308  AFTE14P-GP  [AFTE14P-75]  188.3 122.31 0 top
AFTP6311  AFTE14P-GP  [AFTE14P-75]  184.93 37.65 0 top
AFTP6314  AFTE14P-GP  [AFTE14P-75]  186.07 43.52 0 top
AFTP8902  AFTE14P-GP  [AFTE14P-75]  174.42 135.8 0 top
AFTP8903  AFTE14P-GP  [AFTE14P-75]  174.42 133.8 0 top
AFTP8904  AFTE14P-GP  [AFTE14P-75]  175.35 132.12 0 top
BATT1  SYN-CON8-9-GP-U  [200277MR008G121ZR-U]  155.25 179.77 0 bottom
C715  SC10U6D3V3MX-GP  [C603H38]  130.04 60.85 270 top
C716  SC1U10V2KX-1GP  [C402H22]  126.05 98.68 0 bottom
C717  SC1U10V2KX-1GP  [C402H22]  93.46 100.04 90 bottom
C718  SCD1U16V2KX-3GP  [C402H22]  122.11 76.56 90 top
C719  SC1U10V2KX-1GP  [C402H22]  106.52 63.63 0 top
C720  SCD1U16V2KX-3GP  [C402H22]  121.37 91.25 180 top
C721  SCD1U16V2KX-3GP  [C402H22]  122.2 91.26 180 top
C722  SC1U10V2KX-1GP  [C402H22]  112.03 79.18 270 top
C1101  SC1U10V2KX-1GP  [C402H22]  116.68 90.42 90 top
C1102  SC1U10V2KX-1GP  [C402H22]  114.76 90.46 90 top
C1103  SC1U10V2KX-1GP  [C402H22]  116.92 85.81 90 top
C1116  SC1U10V2KX-1GP  [C402H22]  115.11 98.88 0 bottom
C1117  SC1U10V2KX-1GP  [C402H22]  115.95 98.88 0 bottom
C1136  SC1U10V2KX-1GP  [C402H22]  106.14 81.22 0 top
C1138  SC1U10V2KX-1GP  [C402H22]  105.32 81.87 0 top
C1147  SC1U10V2KX-1GP  [C402H22]  115.93 112.72 270 bottom
C1148  SC1U10V2KX-1GP  [C402H22]  115.93 110.95 270 bottom
C1149  SC1U10V2KX-1GP  [C402H22]  115.93 111.83 270 bottom
C1150  SC1U10V2KX-1GP  [C402H22]  115.93 110.06 270 bottom
C1151  SC1U10V2KX-1GP  [C402H22]  111.57 80.81 270 top
C1152  SC1U10V2KX-1GP  [C402H22]  111.56 79.99 270 top
C1153  SC1U10V2KX-1GP  [C402H22]  117.86 81.23 180 top
C1154  SC1U10V2KX-1GP  [C402H22]  118.7 81.23 180 top
C1172  SC1U10V2KX-1GP  [C402H22]  143.07 96.6 180 bottom
C1173  SC1U10V2KX-1GP  [C402H22]  145.56 103.05 180 bottom
C1174  SC1U10V2KX-1GP  [C402H22]  148.99 97.67 180 bottom
C1175  SC1U10V2KX-1GP  [C402H22]  165.38 85.56 180 bottom
C1176  SC10U10V5KX-2GP  [C805H54]  166.87 85.3 180 bottom
C1180  SC1U10V2KX-1GP  [C402H22]  120.95 86.05 270 top
C1181  SC22U6D3V3MX-1-GP  [C603H40]  144.47 96.6 180 bottom
C1182  SC22U6D3V5MX-2GP  [C805H58]  147.45 100.08 90 bottom
C1183  SC10U10V5KX-2GP  [C805H54]  159.48 90.78 90 bottom
C1184  SC22U6D3V3MX-1-GP  [C603H40]  142.93 100.28 270 bottom
C1201  SCD1U16V2KX-3GP  [C402H22]  104.26 29.49 180 top
C1202  SCD1U16V2KX-3GP  [C402H22]  105.15 29.49 180 top
C1203  SCD1U16V2KX-3GP  [C402H22]  125.6 38.08 180 top
C1204  SCD1U16V2KX-3GP  [C402H22]  60.58 38.18 0 top
C1205  SC2D2U10V3KX-1GP  [C603H36]  59.49 38.19 0 top
C1206  SCD1U16V2KX-3GP  [C402H22]  61.43 38.19 0 top
C1207  SC10U6D3V3MX-GP  [C603H38]  121.92 30.09 180 top
C1208  SC10U6D3V3MX-GP  [C603H38]  106.82 38.48 0 top
C1209  SC10U6D3V3MX-GP  [C603H38]  104.13 38.51 0 top
C1210  SCD1U16V2KX-3GP  [C402H22]  137.53 24.1 180 top
C1211  SCD1U16V2KX-3GP  [C402H22]  77.68 36.79 90 top
C1212  SC1U10V2KX-1GP  [C402H22]  88.97 31.32 180 top
C1213  SC1U10V2KX-1GP  [C402H22]  114.37 18.67 180 top
C1214  SC1U10V2KX-1GP  [C402H22]  126.65 35.2 90 top
C1215  SC1U10V2KX-1GP  [C402H22]  126.65 36.09 90 top
C1216  SC1U10V2KX-1GP  [C402H22]  126.69 34.33 90 top
C1217  SCD1U16V2KX-3GP  [C402H22]  71.73 30.04 180 top
C1218  SCD1U16V2KX-3GP  [C402H22]  103.37 29.49 180 top
C1220  SCD1U16V2KX-3GP  [C402H22]  77.34 30.23 180 top
C1221  SCD1U16V2KX-3GP  [C402H22]  84.53 30.33 180 top
C1222  SCD1U16V2KX-3GP  [C402H22]  86.55 36.57 0 top
C1301  SCD1U16V2KX-3GP  [C402H22]  85.62 17.14 180 top
C1302  SCD1U16V2KX-3GP  [C402H22]  78.11 24.67 90 top
C1303  SC1U10V2KX-1GP  [C402H22]  139.82 19.56 270 top
C1304  SC1U10V2KX-1GP  [C402H22]  139.82 18.75 270 top
C1305  SC2D2U10V3KX-1GP  [C603H36]  61.47 36.06 90 top
C1306  SCD1U16V2KX-3GP  [C402H22]  117.62 19.46 90 top
C1307  SC1U10V2KX-1GP  [C402H22]  140.36 25.73 0 top
C1308  SCD1U16V2KX-3GP  [C402H22]  117.62 20.27 90 top
C1309  SCD1U16V2KX-3GP  [C402H22]  117.62 21.09 90 top
C1310  SCD1U16V2KX-3GP  [C402H22]  78.11 23.83 90 top
C1311  SCD1U16V2KX-3GP  [C402H22]  139.09 24.44 270 top
C1312  SCD1U16V2KX-3GP  [C402H22]  102.3 23.09 180 top
C1313  SCD1U16V2KX-3GP  [C402H22]  105.95 22.54 0 top
C1314  SCD1U16V2KX-3GP  [C402H22]  109.35 23.32 0 top
C1315  SCD1U16V2KX-3GP  [C402H22]  111.22 24.68 0 top
C1316  SCD1U16V2KX-3GP  [C402H22]  104.51 16.98 180 top
C1317  SC10U6D3V3MX-GP  [C603H38]  124.77 31.28 180 top
C1318  SC10U6D3V3MX-GP  [C603H38]  113.96 38.51 0 top
C1321  SC1U10V2KX-1GP  [C402H22]  110.81 17.83 180 top
C1322  SC1U10V2KX-1GP  [C402H22]  115.17 24.42 0 top
C1323  SC10U6D3V3MX-GP  [C603H38]  120.37 38.41 0 top
C1601  SCD1U16V2KX-3GP  [C402H22]  127.32 101.92 180 bottom
C1602  SCD1U16V2KX-3GP  [C402H22]  128.21 101.92 180 bottom
C1603  SCD1U16V2KX-3GP  [C402H22]  124.54 101.72 180 bottom
C1604  SCD1U16V2KX-3GP  [C402H22]  123.65 101.72 180 bottom
C1605  SCD22U10V2KX-1GP  [C402H22]  130.61 102.72 180 bottom
C1606  SCD22U10V2KX-1GP  [C402H22]  131.5 102.72 180 bottom
C1607  SCD22U10V2KX-1GP  [C402H22]  132.36 103.41 180 bottom
C1608  SCD22U10V2KX-1GP  [C402H22]  133.21 103.43 180 bottom
C1609  SCD22U10V2KX-1GP  [C402H22]  130.27 104.69 180 bottom
C1610  SCD22U10V2KX-1GP  [C402H22]  129.44 104.7 180 bottom
C1611  SCD22U10V2KX-1GP  [C402H22]  126.44 104.1 180 bottom
C1612  SCD22U10V2KX-1GP  [C402H22]  125.55 104.1 180 bottom
C1701  SC220P50V2KX-3GP  [C402H22]  156.95 73.6 180 bottom
C1702  SCD1U16V2KX-3GP  [C402H22]  93.01 102.71 0 bottom
C1703  SCD1U16V2KX-3GP  [C402H22]  153.56 40.34 270 top
C1704  SC10U10V5KX-2GP  [C805H54]  147.45 101.89 90 bottom
C1801  SC15P50V2JN-2-GP  [C402H22]  119.91 102.74 270 bottom
C1802  SC15P50V2JN-2-GP  [C402H22]  121.66 102.74 90 bottom
C1803  SC5P50V2CN-2GP  [C402H22]  146.64 77.98 0 bottom
C1804  SC5P50V2CN-2GP  [C402H22]  146.63 76.27 180 bottom
C1901  SC1U10V2KX-1GP  [C402H22]  138.27 61.91 180 top
C1902  SC1U10V2KX-1GP  [C402H22]  133.93 60.2 0 top
C2101  SC1U10V2KX-1GP  [C402H22]  120.96 85.22 270 top
C2102  SC1U10V2KX-1GP  [C402H22]  120.52 83.93 270 top
C2103  SC1U10V2KX-1GP  [C402H22]  139.27 77.99 270 bottom
C2104  SC1U10V2KX-1GP  [C402H22]  123.81 88.03 0 top
C2105  SC1U10V2KX-1GP  [C402H22]  121.29 83.05 270 top
C2106  SC1U10V2KX-1GP  [C402H22]  125.77 84.1 180 top
C2107  SC1U10V2KX-1GP  [C402H22]  124.69 86.3 180 top
C2108  SC1U10V2KX-1GP  [C402H22]  140.46 83.71 270 bottom
C2109  SC1U10V2KX-1GP  [C402H22]  143.12 80.42 180 top
C2110  SCD1U16V2KX-3GP  [C402H22]  143.94 80.42 180 top
C2111  SCD1U16V2KX-3GP  [C402H22]  144.75 80.42 180 top
C2112  SCD1U16V2KX-3GP  [C402H22]  137.59 64.25 180 bottom
C2113  SC22U6D3V3MX-1-GP  [C603H40]  144.19 102.7 180 bottom
C2114  SC22U6D3V3MX-1-GP  [C603H40]  139.14 102.67 270 bottom
C2115  SC22U6D3V3MX-1-GP  [C603H40]  142.36 102.7 180 bottom
C2116  SC1U10V2KX-1GP  [C402H22]  130.97 98.62 0 bottom
C2117  SC1U10V2KX-1GP  [C402H22]  134.74 56.67 0 top
C2118  SCD1U16V2KX-3GP  [C402H22]  135.58 56.66 0 top
C2119  SCD1U16V2KX-3GP  [C402H22]  136.4 56.66 0 top
C2120  SC1U10V2KX-1GP  [C402H22]  156.89 119.14 270 bottom
C2402  SC220P50V2KX-3GP  [C402H22]  175.63 86.14 90 top
C2403  SC47P50V2JN-3GP  [C402H22]  161.1 73.29 180 top
C2405  SC100P50V2JN-3GP  [C402H22]  170.61 67.95 270 top
C2406  SCD1U16V2KX-3GP  [C402H22]  171.05 67.09 270 top
C2407  SCD1U16V2KX-3GP  [C402H22]  184.56 52.92 270 top
C2408  SCD1U16V2KX-3GP  [C402H22]  174.49 54.89 180 top
C2409  SCD01U50V2KX-1GP  [C402H22]  191.9 76.89 0 top
C2410  SCD1U16V2KX-3GP  [C402H22]  171.44 74.63 180 top
C2411  SCD1U16V2KX-3GP  [C402H22]  171.57 73.33 270 top
C2412  SCD1U16V2KX-3GP  [C402H22]  184.21 84.56 180 top
C2413  SCD1U16V2KX-3GP  [C402H22]  191.97 74.64 90 top
C2414  SCD1U16V2KX-3GP  [C402H22]  178.01 60.23 270 top
C2415  SC2D2U10V3KX-1GP  [C603H36]  180.04 59.11 90 top
C2416  SCD1U16V2KX-3GP  [C402H22]  181.54 63.64 180 top
C2417  SC2D2U10V3KX-1GP  [C603H36]  174.1 85.17 180 top
C2418  SC1U10V2KX-1GP  [C402H22]  191.55 73.37 0 top
C2420  SCD1U16V2KX-3GP  [C402H22]  183.38 84.56 180 top
C2421  SCD1U16V2KX-3GP  [C402H22]  180.67 63.52 180 top
C2422  SCD1U16V2KX-3GP  [C402H22]  183.02 64.11 270 top
C2423  SCD1U16V2KX-3GP  [C402H22]  178.91 88.81 90 top
C2424  SC10P50V2JN-4GP  [C402H22]  177.68 62.07 180 top
C2425  SC10P50V2JN-4GP  [C402H22]  177.68 63.82 0 top
C2426  SC1U10V2KX-1GP  [C402H22]  188.07 64.36 0 top
C2427  SC2200P50V2KX-2GP  [C402H22]  182.43 66.25 270 bottom
C2428  SCD1U16V2KX-3GP  [C402H22]  187.25 66.71 0 bottom
C2429  SCD1U16V2KX-3GP  [C402H22]  186.39 75.91 180 bottom
C2435  SC2200P50V2KX-2GP  [C402H22]  180.12 57.08 0 top
C2441  SC2200P50V2KX-2GP  [C402H22]  184.14 66.24 90 bottom
C2501  SC10U10V5KX-2GP  [C805H54]  137.26 61.9 90 bottom
C2502  SCD1U16V2KX-3GP  [C402H22]  137.36 60.57 90 bottom
C2503  SCD22U10V2KX-1GP  [C402H22]  53.38 10.43 180 bottom
C2504  SCD1U16V2KX-3GP  [C402H22]  149.32 52.2 0 bottom
C2505  SC10U10V5KX-2GP  [C805H54]  150.67 52.25 0 bottom
C2601  SC10U6D3V3MX-GP  [C603H38]  158.15 99.29 270 bottom
C2602  SCD1U16V2KX-3GP  [C402H22]  159.76 99.26 0 bottom
C2603  SC2200P50V2KX-2GP  [C402H22]  98.72 140.14 90 top
C2604  SC4D7U6D3V3KX-GP  [C603H36]  98.55 141.76 180 top
C2605  SCD1U16V2KX-3GP  [C402H22]  97.42 138.95 270 bottom
C2606  SC470P50V2KX-3GP  [C402H22]  158.58 96.7 180 bottom
C2607  SC2200P50V2KX-2GP  [C402H22]  51.56 61.37 180 bottom
C2608  SCD1U16V2KX-3GP  [C402H22]  150.25 97.21 90 bottom
C2609  SCD1U16V2KX-3GP  [C402H22]  150.24 96.26 90 bottom
C2610  SCD1U16V2KX-3GP  [C402H22]  162.82 98.69 270 bottom
C2611  SC4D7U6D3V3KX-GP  [C603H36]  97.52 140.02 270 bottom
C2612  SCD1U16V2KX-3GP  [C402H22]  152.65 99.47 0 bottom
C2613  SC100P50V2JN-3GP  [C402H22]  193.92 71.49 0 top
C2701  SC4D7U6D3V3KX-GP  [C603H36]  20.95 8.65 270 top
C2702  SC4D7U6D3V3KX-GP  [C603H36]  20.92 18.62 90 top
C2703  SC1U10V2KX-1GP  [C402H22]  21.73 12.98 270 top
C2704  SC1U10V2KX-1GP  [C402H22]  21.78 13.8 90 top
C2705  SC2D2U10V3KX-1GP  [C603H36]  20.92 17.32 90 top
C2706  SC10U6D3V3MX-GP  [C603H38]  27.65 8.47 0 top
C2707  SCD1U16V2KX-3GP  [C402H22]  33.5 10.22 180 top
C2708  SC10U6D3V3MX-GP  [C603H38]  26.35 8.47 0 top
C2709  SCD1U16V2KX-3GP  [C402H22]  29.16 7.66 270 top
C2710  SCD1U16V2KX-3GP  [C402H22]  21.15 21.01 180 top
C2711  SC4D7U6D3V3KX-GP  [C603H36]  22.22 20.53 180 top
C2712  SC10U6D3V3MX-GP  [C603H38]  22.4 10.65 180 top
C2713  SC10U6D3V3MX-GP  [C603H38]  25.25 23.19 180 top
C2714  SCD1U16V2KX-3GP  [C402H22]  20.61 7.61 270 top
C2715  SC4D7U6D3V3KX-GP  [C603H36]  24.3 9.57 270 top
C2716  SC4D7U6D3V3KX-GP  [C603H36]  30.18 27.01 270 top
C2717  SCD1U16V2KX-3GP  [C402H22]  31.81 12.56 180 top
C2718  SC4D7U6D3V3KX-GP  [C603H36]  34.28 17.43 90 top
C2719  SCD1U16V2KX-3GP  [C402H22]  33.02 19.31 90 top
C2720  SCD1U16V2KX-3GP  [C402H22]  31.7 23.85 0 top
C2721  SCD1U16V2KX-3GP  [C402H22]  24.48 10.62 270 top
C2723  SC22P50V2JN-4GP  [C402H22]  35.56 14.69 270 top
C2907  SC4D7U6D3V3KX-GP  [C603H36]  21.77 22.52 270 top
C2908  SC4D7U6D3V3KX-GP  [C603H36]  21.77 23.82 270 top
C3101  SC15P50V2JN-2-GP  [C402H22]  46.71 174.39 90 top
C3102  SCD1U16V2KX-3GP  [C402H22]  51.29 172.44 180 top
C3103  SC4D7U6D3V3KX-GP  [C603H36]  42.25 171.77 270 top
C3104  SC4D7U6D3V3KX-GP  [C603H36]  41.82 163.29 0 top
C3105  SCD1U16V2KX-3GP  [C402H22]  42.96 163.04 0 top
C3106  SCD1U16V2KX-3GP  [C402H22]  53.34 173.39 180 top
C3107  SC15P50V2JN-2-GP  [C402H22]  45.02 174.4 270 top
C3108  SCD1U16V2KX-3GP  [C402H22]  60.73 176.15 180 top
C3109  SCD1U16V2KX-3GP  [C402H22]  51.86 165.76 90 top
C3110  SC1U10V2KX-1GP  [C402H22]  59.01 172.61 0 top
C3111  SCD1U16V2KX-3GP  [C402H22]  51.86 164.93 90 top
C3112  SCD1U16V2KX-3GP  [C402H22]  52.52 173.38 180 top
C3113  SC1U10V2KX-1GP  [C402H22]  48.65 168.36 90 bottom
C3114  SCD1U16V2KX-3GP  [C402H22]  44.32 167.44 270 bottom
C3115  SCD1U16V2KX-3GP  [C402H22]  41.85 169.94 270 top
C3116  SCD1U16V2KX-3GP  [C402H22]  42.51 173.79 270 top
C3117  SCD1U16V2KX-3GP  [C402H22]  44.32 168.35 270 bottom
C3118  SCD1U16V2KX-3GP  [C402H22]  48.65 167.54 90 bottom
C3119  SCD01U50V2KX-1GP  [C402H22]  30.14 177.66 90 top
C3201  SC100P3KV8JN-2-GP  [C1808H56]  23.64 172.37 90 top
C3406  SCD1U16V2KX-3GP  [C402H22]  182.62 28.6 270 bottom
C3504  SCD1U16V2KX-3GP  [C402H22]  186.46 37.54 90 bottom
C3507  SCD1U16V2KX-3GP  [C402H22]  18.84 40.75 0 top
C3508  SC1U10V2KX-1GP  [C402H22]  19.73 40.75 0 top
C3509  SCD1U16V2KX-3GP  [C402H22]  16.39 35 180 top
C3510  SC1U10V2KX-1GP  [C402H22]  26.23 41.43 180 top
C3511  SC1U10V2KX-1GP  [C402H22]  23.12 35.41 270 top
C3512  SC22U6D3V5MX-2GP  [C805H58]  19.43 43.32 180 top
C3513  SC22U6D3V5MX-2GP  [C805H58]  21.33 43.32 180 top
C3514  SC22U6D3V5MX-2GP  [C805H58]  16.26 32.14 0 top
C3515  SC22U6D3V5MX-2GP  [C805H58]  183.04 37.92 180 bottom
C3516  SC1U10V2KX-1GP  [C402H22]  15.55 35 180 top
C3517  SCD1U16V2KX-3GP  [C402H22]  180.75 37.92 180 bottom
C3518  SC1U10V2KX-1GP  [C402H22]  181.64 37.92 180 bottom
C3519  SC22U6D3V5MX-2GP  [C805H58]  18.1 32.14 0 top
C3601  SCD1U16V2KX-3GP  [C402H22]  22.31 43.83 90 bottom
C3602  SCD1U16V2KX-3GP  [C402H22]  22.31 44.72 90 bottom
C3603  SCD1U16V2KX-3GP  [C402H22]  20.62 40.75 0 top
C3604  SCD1U16V2KX-3GP  [C402H22]  22.5 34.17 90 bottom
C3605  SCD1U16V2KX-3GP  [C402H22]  22.5 35.01 90 bottom
C3618  SCD1U16V2KX-3GP  [C402H22]  14.71 35 180 top
C4001  SC470P50V2KX-3GP  [C402H22]  38.07 27.18 0 top
C4002  SC470P50V2KX-3GP  [C402H22]  37.18 27.18 0 top
C4003  SCD1U16V2KX-3GP  [C402H22]  33.01 56.09 180 top
C4004  SC10U10V5KX-2GP  [C805H54]  34.37 29.77 270 top
C4005  SC10U10V5KX-2GP  [C805H54]  40.81 29.56 180 top
C4006  SCD1U16V2KX-3GP  [C402H22]  164.97 123.35 0 bottom
C4007  SC10U10V5KX-2GP  [C805H54]  157.91 122.86 0 bottom
C4008  SCD1U16V2KX-3GP  [C402H22]  158.46 114.86 90 bottom
C4009  SC4D7U6D3V3KX-GP  [C603H36]  31.67 56.09 180 bottom
C4012  SC10U10V5KX-2GP  [C805H54]  167.54 112.89 0 bottom
C4013  SC10U10V5KX-2GP  [C805H54]  162.84 112.03 270 bottom
C4014  SCD1U16V2KX-3GP  [C402H22]  157.55 131.36 0 bottom
C4016  SC10U10V5KX-2GP  [C805H54]  162.59 118.87 270 bottom
C4017  SC22U6D3V3MX-1-GP  [C603H40]  171.83 98.45 270 bottom
C4018  SC1U10V2KX-1GP  [C402H22]  167.05 102.29 90 bottom
C4019  SCD1U16V2KX-3GP  [C402H22]  171.57 99.85 270 bottom
C4020  SCD1U16V2KX-3GP  [C402H22]  166.44 95.49 270 bottom
C4021  SC1U10V2KX-1GP  [C402H22]  171.57 100.74 270 bottom
C4028  SCD22U10V2KX-1GP  [C402H22]  47.48 8.53 0 bottom
C4029  SCD1U16V2KX-3GP  [C402H22]  46.67 8.53 0 bottom
C4030  SCD1U16V2KX-3GP  [C402H22]  41.74 8.93 0 bottom
C4031  SC1U10V2KX-1GP  [C402H22]  159.68 118.33 90 bottom
C4032  SC1U10V2KX-1GP  [C402H22]  165.01 121.03 0 bottom
C4101  SC1U10V2KX-1GP  [C402H22]  153.02 86.62 270 bottom
C4102  SC1U10V2KX-1GP  [C402H22]  156.86 82.67 0 bottom
C4201  SCD022U16V2KX-3GP  [C402H22]  57.32 40.45 180 top
C4202  SCD022U16V2KX-3GP  [C402H22]  58.08 47.31 180 top
C4203  SCD022U16V2KX-3GP  [C402H22]  57.34 44.41 180 top
C5401  SCD1U16V2KX-3GP  [C402H22]  17.38 72.7 0 bottom
C5402  SCD1U16V2KX-3GP  [C402H22]  18.92 65.31 90 bottom
C5403  SCD1U16V2KX-3GP  [C402H22]  18.92 64.42 90 bottom
C5404  SCD1U16V2KX-3GP  [C402H22]  18.92 67.47 90 bottom
C5405  SCD1U16V2KX-3GP  [C402H22]  18.92 66.58 90 bottom
C5406  SCD1U16V2KX-3GP  [C402H22]  18.92 63.15 90 bottom
C5407  SCD1U16V2KX-3GP  [C402H22]  18.92 62.26 90 bottom
C5408  SCD1U16V2KX-3GP  [C402H22]  18.92 60.99 90 bottom
C5409  SCD1U16V2KX-3GP  [C402H22]  18.92 60.1 90 bottom
C5505  SC4D7U6D3V3KX-GP  [C603H36]  84.09 154.38 270 bottom
C5508  SCD1U16V2KX-3GP  [C402H22]  80.64 171.35 270 top
C5515  SC1KP50V2KX-1GP  [C402H22]  78.03 177.6 0 bottom
C5516  SC1KP50V2KX-1GP  [C402H22]  96.16 152.61 90 top
C5531  SCD1U16V2KX-3GP  [C402H22]  81.14 173.94 270 top
C5532  SCD1U16V2KX-3GP  [C402H22]  80.64 170.46 270 top
C5533  SCD1U16V2KX-3GP  [C402H22]  81.14 173.05 270 top
C5534  SCD1U16V2KX-3GP  [C402H22]  80.64 169.57 270 top
C5535  SCD1U50V3KX-GP  [C603H36]  96.35 147.57 90 bottom
C5536  SC1U10V2KX-1GP  [C402H22]  80.02 177.6 180 bottom
C5537  SCD1U16V2KX-3GP  [C402H22]  80.64 168.69 270 top
C5538  SCD1U16V2KX-3GP  [C402H22]  80.84 177.6 0 bottom
C5539  SC4D7U6D3V3KX-GP  [C603H36]  75.66 161.4 90 bottom
C5540  SC10P50V2JN-4GP  [C402H22]  80.67 153.04 270 top
C5541  SC10P50V2JN-4GP  [C402H22]  83.87 152.61 180 top
C5542  SCD1U50V3KX-GP  [C603H36]  96.69 148.12 180 top
C6001  SCD1U16V2KX-3GP  [C402H22]  177.54 34.57 90 bottom
C6002  SC10U10V5KX-2GP  [C805H54]  177.41 33.18 90 bottom
C6003  SCD22U10V2KX-1GP  [C402H22]  178.3 25.43 270 bottom
C6004  SCD22U10V2KX-1GP  [C402H22]  178.3 24.54 270 bottom
C6005  SCD22U10V2KX-1GP  [C402H22]  178.3 22.51 90 bottom
C6006  SCD22U10V2KX-1GP  [C402H22]  178.3 23.4 90 bottom
C6007  SCD1U16V2KX-3GP  [C402H22]  183.38 32.8 0 bottom
C6008  SC10U10V5KX-2GP  [C805H54]  181.99 33.18 0 bottom
C6009  SC4700P50V2KX-1GP  [C402H22]  177.4 31.92 0 top
C6107  SCD1U16V2KX-3GP  [C402H22]  164.08 38.56 0 top
C6108  SC4D7U6D3V3KX-GP  [C603H36]  167.23 38.51 0 top
C6109  SCD1U16V2KX-3GP  [C402H22]  164.89 38.56 0 top
C6110  SC470P50V2KX-3GP  [C402H22]  167.69 66.12 0 bottom
C6111  SC470P50V2KX-3GP  [C402H22]  168.53 66.12 0 bottom
C6112  SC10U6D3V3MX-GP  [C603H38]  165.96 38.51 0 top
C6113  SC4700P50V2KX-1GP  [C402H22]  163.14 58.78 90 top
C6401  SCD1U16V2KX-3GP  [C402H22]  214.62 153.27 270 top
C6501  SCD1U16V2KX-3GP  [C402H22]  195.64 102.85 0 top
C6502  SCD1U16V2KX-3GP  [C402H22]  195.37 109.07 180 top
C6503  SCD1U16V2KX-3GP  [C402H22]  44.32 76.36 0 top
C6504  SCD1U16V2KX-3GP  [C402H22]  57.4 71.66 0 top
C6701  SCD1U16V2KX-3GP  [C402H22]  168.82 93.21 90 bottom
C6702  SCD1U16V2KX-3GP  [C402H22]  168.82 94.1 90 bottom
C6703  SC10U6D3V3MX-GP  [C603H38]  175 94.14 270 bottom
C7301  SCD22U10V2KX-1GP  [C402H22]  178.38 140.87 90 top
C7302  SCD22U10V2KX-1GP  [C402H22]  178.38 141.68 90 top
C7303  SCD22U10V2KX-1GP  [C402H22]  175.79 140.88 90 top
C7304  SCD22U10V2KX-1GP  [C402H22]  175.79 140.07 90 top
C7305  SCD22U10V2KX-1GP  [C402H22]  174.01 142.37 90 top
C7306  SCD22U10V2KX-1GP  [C402H22]  174.01 143.23 90 top
C7307  SCD22U10V2KX-1GP  [C402H22]  175.71 143.73 90 top
C7308  SCD22U10V2KX-1GP  [C402H22]  175.71 144.55 90 top
C7310  SC4D7U6D3V3KX-GP  [C603H36]  175.97 146.51 0 top
C7312  SC1U10V2KX-1GP  [C402H22]  185.69 145.9 0 top
C7315  SC4D7U6D3V3KX-GP  [C603H36]  197.51 140.87 270 top
C7316  SCD1U25V2KX-GP  [C402H22]  180.33 127.51 0 top
C7317  SC4D7U6D3V3KX-GP  [C603H36]  183.89 146.23 180 top
C7318  SCD1U16V2KX-3GP  [C402H22]  184.38 143.78 270 top
C7319  SC1U10V2KX-1GP  [C402H22]  184.39 144.63 270 top
C7323  SC10U6D3V3MX-GP  [C603H38]  176.37 147.58 180 bottom
C7324  SC4D7U6D3V3KX-GP  [C603H36]  184.45 127.61 0 top
C7326  SC22U6D3V3MX-1-GP  [C603H40]  157.16 160.59 0 bottom
C7501  SCD1U16V2KX-3GP  [C402H22]  182.19 152.53 270 top
C7502  SCD1U16V2KX-3GP  [C402H22]  188.18 153.27 0 top
C7505  SCD1U16V2KX-3GP  [C402H22]  192.48 146.89 0 top
C7506  SCD1U16V2KX-3GP  [C402H22]  199.13 145.23 180 top
C7507  SC1U10V3KX-4GP-U  [C603H36]  205.25 150.17 270 top
C7513  SC4D7U6D3V3KX-GP  [C603H36]  197.51 142.16 270 top
C7514  SC4D7U6D3V3KX-GP  [C603H36]  197.53 145.44 270 top
C7517  SC10U10V5KX-2GP  [C805H54]  167.84 164.6 270 top
C7518  SC22U6D3V3MX-1-GP  [C603H40]  187.57 144.67 270 top
C7520  SC22U6D3V3MX-1-GP  [C603H40]  167.69 169.52 270 top
C7525  SC1U10V3KX-4GP-U  [C603H36]  190.7 153.57 0 top
C7601  SCD1U16V2KX-3GP  [C402H22]  194.41 134.04 90 top
C7602  SCD1U16V2KX-3GP  [C402H22]  194.41 134.88 90 top
C7603  SC4D7U6D3V3KX-GP  [C603H36]  193.01 131.25 270 top
C7604  SC10U6D3V3MX-GP  [C603H38]  194.2 132.92 90 top
C7605  SCD1U16V2KX-3GP  [C402H22]  196.76 135.63 90 top
C7606  SC2D2U10V2KX-GP  [C402H22]  196.76 134.74 90 top
C7607  SC18P50V2JN-1-GP  [C402H22]  208.68 138.97 180 bottom
C7608  SC18P50V2JN-1-GP  [C402H22]  208.68 137.27 0 bottom
C7609  SC2700P50V2KX-1-GP  [C402H22]  189.52 125.16 90 bottom
C7610  SC2700P50V2KX-1-GP  [C402H22]  191.43 124.86 90 bottom
C7701  SC4D7U6D3V3KX-GP  [C603H36]  214.7 137.98 0 bottom
C7702  SC4D7U6D3V3KX-GP  [C603H36]  194.61 147.07 90 top
C7703  SC4D7U6D3V3KX-GP  [C603H36]  204.34 138.99 0 top
C7704  SC4D7U6D3V3KX-GP  [C603H36]  183.13 127.62 0 top
C7708  SC4D7U6D3V3KX-GP  [C603H36]  194.28 137.6 0 top
C7709  SC4D7U6D3V3KX-GP  [C603H36]  217.99 137.55 270 bottom
C7710  SC22U6D3V3MX-1-GP  [C603H40]  218.14 134.21 270 bottom
C7711  SC1U10V2KX-1GP  [C402H22]  195.83 137.27 0 top
C7712  SC1U10V2KX-1GP  [C402H22]  195.9 142.53 0 top
C7713  SC1U10V2KX-1GP  [C402H22]  188 141.37 270 top
C7714  SC1U10V2KX-1GP  [C402H22]  195.9 144.72 0 top
C7717  SC22U6D3V3MX-1-GP  [C603H40]  218.14 136.01 270 bottom
C7719  SC4D7U6D3V3KX-GP  [C603H36]  190.27 140.82 0 top
C7720  SC4D7U6D3V3KX-GP  [C603H36]  187.97 140.29 270 top
C7721  SC4D7U6D3V3KX-GP  [C603H36]  215.99 137.98 0 bottom
C7722  SC4D7U6D3V3KX-GP  [C603H36]  192.24 144.84 0 top
C7723  SC4D7U6D3V3KX-GP  [C603H36]  190.25 144.84 0 top
C7724  SC4D7U6D3V3KX-GP  [C603H36]  194.28 142.36 0 top
C7725  SC4D7U6D3V3KX-GP  [C603H36]  187.9 142.52 270 top
C7726  SC4D7U6D3V3KX-GP  [C603H36]  194.28 144.74 0 top
C7728  SC1U10V2KX-1GP  [C402H22]  203.27 138.66 0 top
C7729  SCD1U16V2KX-3GP  [C402H22]  197.73 138.84 270 top
C7730  SC4D7U6D3V3KX-GP  [C603H36]  194.28 139.98 0 top
C7731  SC4D7U6D3V3KX-GP  [C603H36]  192.24 142.42 0 top
C7732  SC4D7U6D3V3KX-GP  [C603H36]  192.45 140.03 0 top
C7734  SCD1U16V2KX-3GP  [C402H22]  197.73 139.66 270 top
C7735  SCD1U16V2KX-3GP  [C402H22]  182.04 127.53 0 top
C7736  SC1U10V2KX-1GP  [C402H22]  181.19 127.53 0 top
C7803  SC820P50V2KX-1GP  [C402H22]  200.32 161.52 270 bottom
C7804  SCD1U16V2KX-3GP  [C402H22]  205.86 176.18 180 top
C7805  SC1U10V3KX-4GP-U  [C603H36]  196.39 176.31 180 top
C7810  SC1U10V3KX-4GP-U  [C603H36]  197.66 176.31 180 top
C7811  SC1U10V3KX-4GP-U  [C603H36]  212.54 155.63 90 top
C7812  SC1U10V3KX-4GP-U  [C603H36]  202.69 176.43 180 top
C7813  SC10U6D3V3MX-GP  [C603H38]  206.3 161.36 90 top
C7814  SC1U10V3KX-4GP-U  [C603H36]  203.31 160.38 90 bottom
C7815  SC10U6D3V3MX-GP  [C603H38]  208.4 176.43 180 top
C7816  SC1U10V3KX-4GP-U  [C603H36]  212.54 153.75 90 top
C7817  SC1U10V3KX-4GP-U  [C603H36]  207 176.43 180 top
C7820  SCD1U16V2KX-3GP  [C402H22]  202.18 176.05 0 bottom
C7821  SCD1U16V2KX-3GP  [C402H22]  200.15 176.05 0 bottom
C7822  SC1U10V3KX-4GP-U  [C603H36]  195.47 160.81 180 bottom
C7827  SCD1U16V2KX-3GP  [C402H22]  203.46 176.04 0 bottom
C7829  SCD1U16V2KX-3GP  [C402H22]  206.46 176.03 0 bottom
C7830  SCD1U16V2KX-3GP  [C402H22]  205.61 176.05 0 bottom
C7831  SCD1U16V2KX-3GP  [C402H22]  203.64 161.45 90 bottom
C7832  SCD1U16V2KX-3GP  [C402H22]  212.49 152 90 top
C7833  SCD1U16V2KX-3GP  [C402H22]  204.72 176.05 0 bottom
C7834  SCD1U16V2KX-3GP  [C402H22]  198.33 176.03 0 bottom
C7835  SCD1U16V2KX-3GP  [C402H22]  196.65 176.03 0 bottom
C7836  SCD1U16V2KX-3GP  [C402H22]  212.49 150.52 90 top
C7902  SC820P50V2KX-1GP  [C402H22]  178.76 161.54 270 top
C7906  SC1U10V3KX-4GP-U  [C603H36]  172.71 176.43 180 top
C7909  SCD1U16V2KX-3GP  [C402H22]  170.43 176.05 0 bottom
C7910  SCD1U16V2KX-3GP  [C402H22]  171.44 176.05 0 bottom
C7911  SC1U10V3KX-4GP-U  [C603H36]  167.66 171.96 270 top
C7912  SCD1U16V2KX-3GP  [C402H22]  195.36 176.05 0 bottom
C7913  SCD1U16V2KX-3GP  [C402H22]  183.89 176.05 0 bottom
C7915  SC1U10V3KX-4GP-U  [C603H36]  183.91 176.33 180 top
C7916  SC1U10V3KX-4GP-U  [C603H36]  171.32 176.43 180 top
C7917  SC1U10V3KX-4GP-U  [C603H36]  182.51 176.33 180 top
C7919  SC1U10V3KX-4GP-U  [C603H36]  194.18 160.81 180 bottom
C7921  SCD1U16V2KX-3GP  [C402H22]  167.71 167.59 270 top
C7922  SCD1U16V2KX-3GP  [C402H22]  167.71 166.58 270 top
C7923  SCD1U16V2KX-3GP  [C402H22]  183.53 161.6 270 top
C7924  SC1U10V3KX-4GP-U  [C603H36]  174.11 176.43 180 top
C7925  SCD1U16V2KX-3GP  [C402H22]  183 176.05 0 bottom
C7926  SC1U10V3KX-4GP-U  [C603H36]  185.3 176.33 180 top
C7927  SCD1U16V2KX-3GP  [C402H22]  172.46 176.05 0 bottom
C7928  SCD1U16V2KX-3GP  [C402H22]  176.4 176.05 0 bottom
C7929  SCD1U16V2KX-3GP  [C402H22]  175.38 176.05 0 bottom
C7930  SCD1U16V2KX-3GP  [C402H22]  173.86 176.05 0 bottom
C8301  SC10U10V5KX-2GP  [C805H54]  171.8 127.15 90 bottom
C8302  SC470P50V2KX-3GP  [C402H22]  171.24 127.58 270 top
C8303  SCD1U16V2KX-3GP  [C402H22]  145.41 150.24 0 bottom
